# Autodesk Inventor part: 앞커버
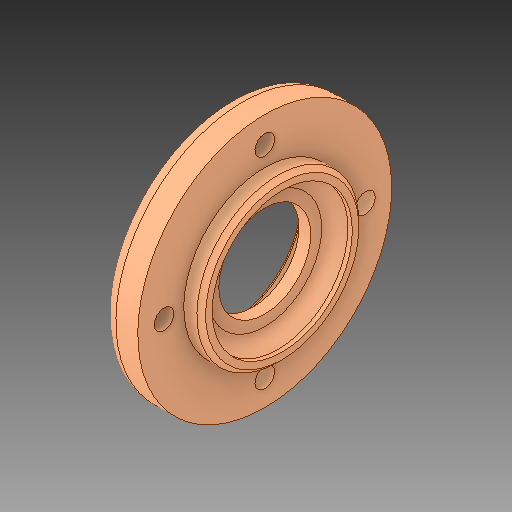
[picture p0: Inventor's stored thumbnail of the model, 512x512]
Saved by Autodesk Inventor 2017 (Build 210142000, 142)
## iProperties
Created: 2024-08
Part Number: 앞커버
Material: 일반
Document SubType Name: Modeling
Designer: MRC
Density: 1 g/cm^3
Appearance: 기본값
Author: jhkim
Sending System: Autodesk Inventor 2025
Preprocessor: ST-DEVELOPER v20
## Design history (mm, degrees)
feature "솔리드1"
node "솔리드2"
